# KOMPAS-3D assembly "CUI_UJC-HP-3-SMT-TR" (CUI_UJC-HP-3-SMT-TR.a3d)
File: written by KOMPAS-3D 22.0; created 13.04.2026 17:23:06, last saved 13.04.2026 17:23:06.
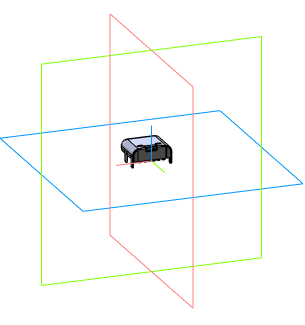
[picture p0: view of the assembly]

Document properties: Автор: Andrey; Полное имя файла: C:\Users\User1\Documents\CUI_UJC-HP-3-SMT-TR.a3d

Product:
- Component [assembly]: UJC-HP-3-SMT-TR  | qty 1  | source file: UJC-HP-3-SMT-TR.a3d
- Part/product: CUI_UJC-HP-3-SMT-TR
    Комментарий: CUI_UJC-HP-3-SMT-TR

Referenced files in C:\Users\User1\Documents\: UJC-HP-3-SMT-TR.a3d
